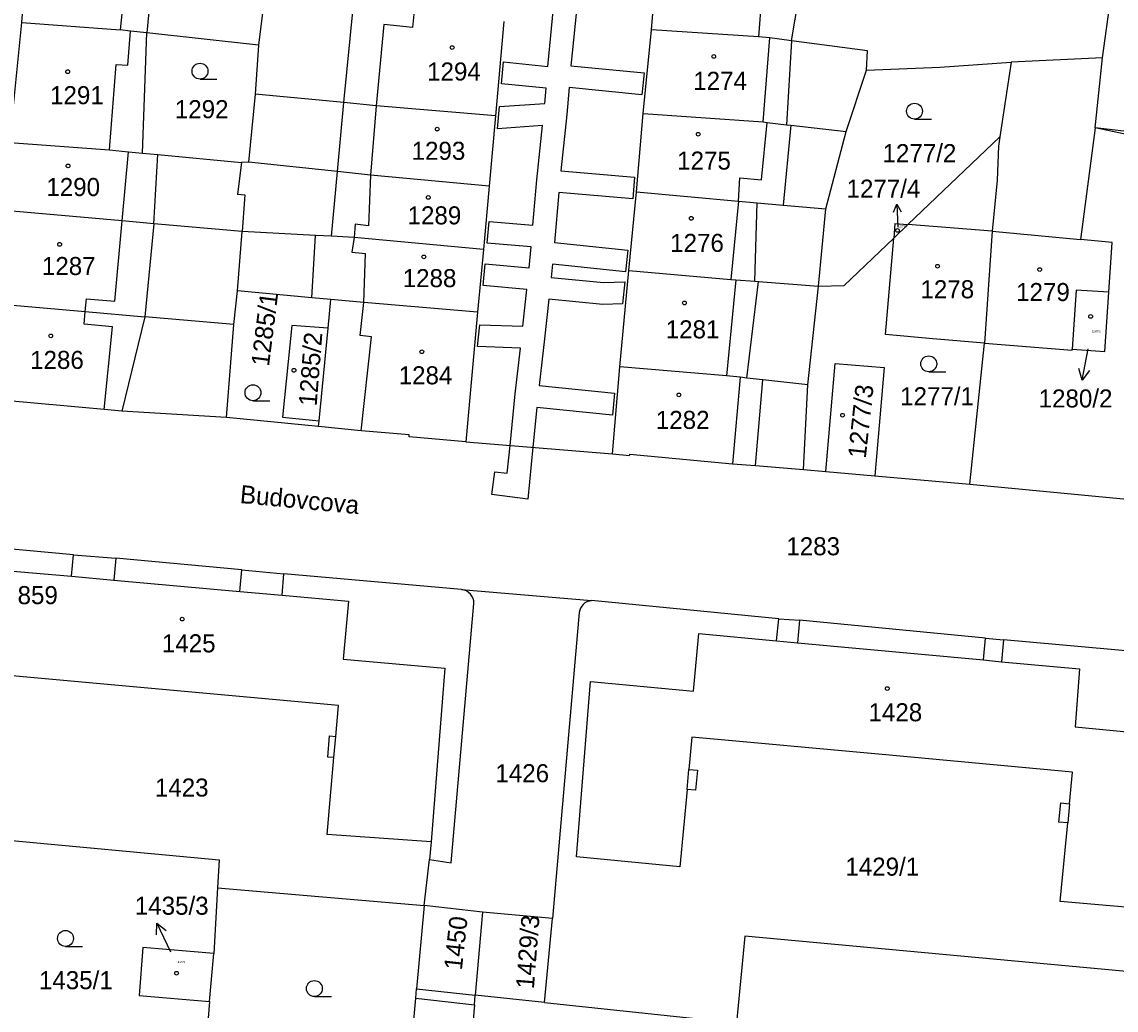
# Model space of a CAD drawing. Extents: x -755819 to -753140, y -1169796 to -1166000.
# Drawn here: x -755595.1 to -755492, y -1167320.5 to -1167227.4 of the extents above; entities that cross this region are included whole.
import ezdxf

# ---------------------------------------------------------------- set-up
doc = ezdxf.new("R2010")
doc.units = 0
for name, color, linetype in [('Vrstva 1', 7, 'Continuous'), ('Vrstva 15', 7, 'Continuous'), ('Vrstva 16', 7, 'Continuous'), ('Vrstva 17', 7, 'Continuous'), ('Vrstva 18', 7, 'Continuous'), ('Vrstva 19', 7, 'Continuous'), ('Vrstva 25', 7, 'Continuous'), ('Vrstva 27', 7, 'Continuous'), ('Vrstva 4', 7, 'Continuous'), ('Vrstva 6', 7, 'Continuous')]:
    doc.layers.add(name, color=color, linetype=linetype)

msp = doc.modelspace()

# ---------------------------------------------------------------- linework, layer by layer
at = {"layer": 'Vrstva 1'}
for p, q in [((-755595.07, -1167227.47), (-755594.03, -1167214.38)), ((-755582.08, -1167215.46), (-755583.31, -1167228.45)), ((-755535.78, -1167228.17), (-755534.86, -1167217.19)), ((-755522.6, -1167229.2), (-755520.73, -1167218.42)), ((-755493.31, -1167230.79), (-755492.14, -1167222.37)), ((-755572.26, -1167225.27), (-755572.79, -1167229.62)), ((-755596.22, -1167238.78), (-755595.07, -1167227.47)), ((-755595.07, -1167227.47), (-755585.82, -1167228.18)), ((-755549.7, -1167227.37), (-755550.46, -1167236.28)), ((-755584.85, -1167228.28), (-755585.82, -1167228.18)), ((-755583.31, -1167228.45), (-755584.85, -1167228.28)), ((-755583.73, -1167239.78), (-755583.31, -1167228.45)), ((-755572.79, -1167229.62), (-755583.31, -1167228.45)), ((-755536.55, -1167236.06), (-755535.78, -1167228.17)), ((-755525.71, -1167228.82), (-755535.78, -1167228.17)), ((-755572.79, -1167229.62), (-755573.09, -1167234.23)), ((-755524.63, -1167228.93), (-755525.71, -1167228.82)), ((-755522.6, -1167229.2), (-755524.63, -1167228.93)), ((-755515.45, -1167230.14), (-755522.6, -1167229.2)), ((-755515.52, -1167231.98), (-755515.45, -1167230.14)), ((-755508.61, -1167231.69), (-755501.92, -1167231.22)), ((-755501.92, -1167231.22), (-755502.97, -1167238.26)), ((-755493.31, -1167230.79), (-755501.92, -1167231.22)), ((-755493.98, -1167237.39), (-755493.31, -1167230.79)), ((-755517.44, -1167237.74), (-755515.52, -1167231.98)), ((-755515.52, -1167231.98), (-755508.61, -1167231.69)), ((-755573.09, -1167234.23), (-755573.72, -1167240.63)), ((-755564.76, -1167235.02), (-755573.09, -1167234.23)), ((-755561.72, -1167235.31), (-755564.76, -1167235.02)), ((-755550.46, -1167236.28), (-755561.72, -1167235.31)), ((-755550.46, -1167236.28), (-755551.06, -1167242.88)), ((-755537.19, -1167243.43), (-755536.55, -1167236.06)), ((-755536.55, -1167236.06), (-755525.26, -1167236.82)), ((-755525.26, -1167236.82), (-755524.9, -1167236.91)), ((-755524.9, -1167236.91), (-755523.07, -1167237.11)), ((-755523.07, -1167237.11), (-755522.67, -1167237.15)), ((-755522.67, -1167237.15), (-755517.44, -1167237.74)), ((-755519.35, -1167245.03), (-755517.44, -1167237.74)), ((-755493.98, -1167237.39), (-755495.36, -1167247.9)), ((-755483.37, -1167239.63), (-755493.98, -1167237.39)), ((-755596.22, -1167238.78), (-755586.81, -1167239.46)), ((-755502.97, -1167238.26), (-755503.1, -1167239.12)), ((-755586.81, -1167239.46), (-755585.02, -1167239.65)), ((-755585.02, -1167239.65), (-755583.73, -1167239.78)), ((-755583.73, -1167239.78), (-755582.28, -1167239.91)), ((-755582.28, -1167239.91), (-755574.4, -1167240.66)), ((-755503.1, -1167239.12), (-755503.23, -1167242.34)), ((-755574.4, -1167240.66), (-755574.78, -1167243.64)), ((-755573.72, -1167240.63), (-755574.4, -1167240.66)), ((-755565.36, -1167241.52), (-755573.72, -1167240.63)), ((-755562.25, -1167241.86), (-755565.36, -1167241.52)), ((-755551.06, -1167242.88), (-755562.25, -1167241.86)), ((-755551.06, -1167242.88), (-755551.6, -1167248.86)), ((-755503.23, -1167242.34), (-755503.68, -1167247.13)), ((-755574.78, -1167243.64), (-755574.07, -1167243.71)), ((-755574.07, -1167243.71), (-755574.34, -1167247.15)), ((-755537.9, -1167250.83), (-755537.19, -1167243.43)), ((-755537.19, -1167243.43), (-755527.6, -1167244.29)), ((-755527.6, -1167244.29), (-755525.82, -1167244.45)), ((-755525.82, -1167244.45), (-755523.39, -1167244.67)), ((-755523.39, -1167244.67), (-755519.35, -1167245.03)), ((-755520.06, -1167252.32), (-755519.35, -1167245.03)), ((-755585.62, -1167246.17), (-755596.7, -1167245.18)), ((-755582.66, -1167246.43), (-755585.62, -1167246.17)), ((-755574.34, -1167247.15), (-755582.66, -1167246.43)), ((-755512.85, -1167246.41), (-755512.97, -1167247.78)), ((-755512.85, -1167246.41), (-755511.63, -1167246.51)), ((-755503.68, -1167247.13), (-755504.41, -1167257.66)), ((-755574.77, -1167252.76), (-755574.34, -1167247.15)), ((-755567.43, -1167247.53), (-755574.34, -1167247.15)), ((-755565.92, -1167247.61), (-755567.43, -1167247.53)), ((-755563.77, -1167247.73), (-755565.92, -1167247.61)), ((-755551.6, -1167248.86), (-755563.77, -1167247.73)), ((-755513.73, -1167256.86), (-755512.97, -1167247.78)), ((-755492.39, -1167248.18), (-755495.36, -1167247.9)), ((-755551.6, -1167248.86), (-755552.16, -1167254.76)), ((-755492.71, -1167252.88), (-755492.39, -1167248.18)), ((-755538.76, -1167259.89), (-755537.9, -1167250.83)), ((-755537.9, -1167250.83), (-755528.31, -1167251.67)), ((-755528.31, -1167251.67), (-755527.82, -1167251.71)), ((-755527.82, -1167251.71), (-755526.05, -1167251.85)), ((-755526.05, -1167251.85), (-755525.71, -1167251.87)), ((-755525.71, -1167251.87), (-755520.06, -1167252.32)), ((-755575.11, -1167255.91), (-755574.77, -1167252.76)), ((-755567.76, -1167253.39), (-755574.77, -1167252.76)), ((-755521.06, -1167261.61), (-755520.06, -1167252.32)), ((-755495.78, -1167252.67), (-755496.17, -1167258.24)), ((-755492.71, -1167252.88), (-755495.78, -1167252.67)), ((-755493.09, -1167258.46), (-755492.71, -1167252.88)), ((-755597.48, -1167253.97), (-755589.12, -1167254.7)), ((-755565.97, -1167253.56), (-755567.76, -1167253.39)), ((-755566.22, -1167256.27), (-755565.97, -1167253.56)), ((-755562.88, -1167253.83), (-755565.97, -1167253.56)), ((-755552.16, -1167254.76), (-755562.88, -1167253.83)), ((-755589.12, -1167254.7), (-755583.49, -1167255.19)), ((-755575.11, -1167255.91), (-755583.49, -1167255.19)), ((-755552.16, -1167254.76), (-755553.25, -1167266.97)), ((-755575.81, -1167264.66), (-755575.11, -1167255.91)), ((-755569.65, -1167256), (-755570.52, -1167264.64)), ((-755566.22, -1167256.27), (-755569.65, -1167256)), ((-755567.09, -1167264.99), (-755566.22, -1167256.27)), ((-755509.27, -1167257.27), (-755513.73, -1167256.86)), ((-755504.41, -1167257.66), (-755509.27, -1167257.27)), ((-755505.81, -1167270.94), (-755504.41, -1167257.66)), ((-755504.41, -1167257.66), (-755496.17, -1167258.34)), ((-755496.17, -1167258.34), (-755496.17, -1167258.24)), ((-755496.17, -1167258.24), (-755493.09, -1167258.46)), ((-755539.46, -1167268.09), (-755538.76, -1167259.89)), ((-755528.7, -1167260.75), (-755538.76, -1167259.89)), ((-755519.36, -1167269.76), (-755518.47, -1167259.58)), ((-755518.47, -1167259.58), (-755513.85, -1167259.98)), ((-755513.85, -1167259.98), (-755514.74, -1167270.16)), ((-755527.44, -1167260.89), (-755528.7, -1167260.75)), ((-755526.8, -1167260.96), (-755527.44, -1167260.89)), ((-755525.29, -1167261.13), (-755526.8, -1167260.96)), ((-755521.06, -1167261.61), (-755525.29, -1167261.13)), ((-755521.45, -1167269.57), (-755521.06, -1167261.61)), ((-755587.34, -1167263.93), (-755598.35, -1167262.92)), ((-755585.65, -1167264.08), (-755587.34, -1167263.93)), ((-755575.81, -1167264.66), (-755585.65, -1167264.08)), ((-755567.14, -1167265.53), (-755575.81, -1167264.66)), ((-755570.52, -1167264.64), (-755567.09, -1167264.99)), ((-755567.14, -1167265.53), (-755567.09, -1167264.99)), ((-755563.13, -1167265.94), (-755567.14, -1167265.53)), ((-755558.6, -1167266.32), (-755563.13, -1167265.94)), ((-755558.61, -1167266.48), (-755558.6, -1167266.32)), ((-755553.25, -1167266.97), (-755558.61, -1167266.48)), ((-755553.25, -1167266.97), (-755539.46, -1167268.09)), ((-755539.46, -1167268.09), (-755537.85, -1167268.24)), ((-755537.85, -1167268.24), (-755537.83, -1167268.12)), ((-755537.83, -1167268.12), (-755528.16, -1167269.04)), ((-755528.16, -1167269.04), (-755525.98, -1167269.21)), ((-755525.98, -1167269.21), (-755521.45, -1167269.57)), ((-755521.45, -1167269.57), (-755519.36, -1167269.76)), ((-755519.36, -1167269.76), (-755514.74, -1167270.16)), ((-755514.74, -1167270.16), (-755505.81, -1167270.94)), ((-755505.81, -1167270.94), (-755488.72, -1167272.57)), ((-755590.22, -1167277.62), (-755598.23, -1167276.87)), ((-755590.22, -1167277.62), (-755586.24, -1167277.92)), ((-755574.37, -1167279.03), (-755586.24, -1167277.92)), ((-755574.37, -1167279.03), (-755570.39, -1167279.39)), ((-755553.68, -1167280.88), (-755570.39, -1167279.39)), ((-755553.68, -1167280.88), (-755541.44, -1167281.92)), ((-755523.8, -1167283.62), (-755541.44, -1167281.92)), ((-755554.63, -1167306.6), (-755552.5, -1167282.19)), ((-755542.58, -1167283.04), (-755545.11, -1167311.85)), ((-755523.99, -1167285.7), (-755523.8, -1167283.62)), ((-755523.8, -1167283.62), (-755521.83, -1167283.77)), ((-755504.32, -1167285.44), (-755521.83, -1167283.77)), ((-755531.81, -1167290.45), (-755531.32, -1167285.02)), ((-755531.32, -1167285.02), (-755523.99, -1167285.7)), ((-755504.32, -1167285.44), (-755502.64, -1167285.61)), ((-755502.64, -1167285.61), (-755502.83, -1167287.67)), ((-755483.86, -1167287.31), (-755502.64, -1167285.61)), ((-755502.83, -1167287.67), (-755495.48, -1167288.35)), ((-755495.48, -1167288.35), (-755495.87, -1167293.8)), ((-755565.26, -1167291.78), (-755597.44, -1167288.87)), ((-755542.85, -1167306.06), (-755541.51, -1167289.53)), ((-755541.51, -1167289.53), (-755531.81, -1167290.45)), ((-755565.52, -1167294.71), (-755565.26, -1167291.78)), ((-755495.87, -1167293.8), (-755486.26, -1167294.72)), ((-755566.25, -1167296.65), (-755566.09, -1167294.66)), ((-755566.09, -1167294.66), (-755565.52, -1167294.71)), ((-755531.98, -1167294.77), (-755532.26, -1167297.82)), ((-755514.06, -1167296.42), (-755531.98, -1167294.77)), ((-755496.12, -1167298.06), (-755514.06, -1167296.42)), ((-755566.31, -1167303.94), (-755565.69, -1167296.7)), ((-755565.69, -1167296.7), (-755566.25, -1167296.65)), ((-755532.26, -1167297.82), (-755531.45, -1167297.89)), ((-755531.45, -1167297.89), (-755531.62, -1167299.77)), ((-755496.4, -1167301.05), (-755496.12, -1167298.06)), ((-755532.43, -1167299.7), (-755533.1, -1167306.99)), ((-755531.62, -1167299.77), (-755532.43, -1167299.7)), ((-755497.41, -1167302.77), (-755497.23, -1167300.97)), ((-755497.23, -1167300.97), (-755496.4, -1167301.05)), ((-755496.58, -1167302.85), (-755497.41, -1167302.77)), ((-755497.29, -1167310.24), (-755496.58, -1167302.85)), ((-755601.97, -1167303.95), (-755576.51, -1167306.32)), ((-755556.52, -1167304.62), (-755566.31, -1167303.94)), ((-755556.52, -1167304.62), (-755556.7, -1167306.29)), ((-755576.51, -1167306.32), (-755576.65, -1167308.96)), ((-755557.18, -1167310.63), (-755556.7, -1167306.29)), ((-755556.7, -1167306.29), (-755554.63, -1167306.6)), ((-755533.1, -1167306.99), (-755542.85, -1167306.06)), ((-755576.65, -1167308.96), (-755557.18, -1167310.63)), ((-755557.18, -1167310.63), (-755557.9, -1167318.49)), ((-755551.68, -1167311.25), (-755557.18, -1167310.63)), ((-755487.4, -1167311.1), (-755497.29, -1167310.24)), ((-755551.68, -1167311.25), (-755552.38, -1167319.08)), ((-755545.11, -1167311.85), (-755551.68, -1167311.25)), ((-755545.87, -1167319.76), (-755545.11, -1167311.85)), ((-755527, -1167313.51), (-755527.77, -1167321.67)), ((-755486.66, -1167317.24), (-755527, -1167313.51)), ((-755583.67, -1167314.58), (-755584.03, -1167319.09)), ((-755577.01, -1167315.15), (-755583.67, -1167314.58)), ((-755577.39, -1167319.66), (-755577.01, -1167315.15)), ((-755584.03, -1167319.09), (-755577.39, -1167319.66)), ((-755557.98, -1167319.34), (-755557.9, -1167318.49)), ((-755552.45, -1167319.97), (-755552.38, -1167319.08)), ((-755545.87, -1167319.76), (-755552.38, -1167319.08)), ((-755559.43, -1167335.26), (-755557.98, -1167319.34)), ((-755557.98, -1167319.34), (-755552.45, -1167319.97)), ((-755552.45, -1167319.97), (-755553.02, -1167326.32)), ((-755545.87, -1167319.76), (-755529.57, -1167321.48))]:
    msp.add_line(p, q, dxfattribs=at)
for centre, radius, start, end in [((-755553.8, -1167282.17), 1.3, 359.2739, 84.7489), ((-755541.35, -1167283.15), 1.23, 94.16, 174.826)]:
    msp.add_arc(centre, radius, start, end, dxfattribs=at)
at = {"layer": 'Vrstva 16'}
for p, q in [((-755512.68, -1167244.6), (-755512.57, -1167246.76)), ((-755495.21, -1167261.15), (-755494.66, -1167258.2)), ((-755582.37, -1167312.29), (-755581.09, -1167315))]:
    msp.add_line(p, q, dxfattribs=at)
for points in [[(-755513, -1167245.34), (-755512.68, -1167244.6), (-755512.28, -1167245.3)], [(-755494.54, -1167260.26), (-755495.21, -1167261.15), (-755495.52, -1167260.07)], [(-755582.39, -1167313.4), (-755582.37, -1167312.29), (-755581.49, -1167312.98)]]:
    msp.add_lwpolyline(points, dxfattribs=at)
at = {"layer": 'Vrstva 25'}
for p, q in [((-755578.3, -1167232.81), (-755576.7, -1167232.81)), ((-755511.01, -1167236.58), (-755509.41, -1167236.58)), ((-755509.67, -1167260.37), (-755508.07, -1167260.37)), ((-755573.31, -1167263.09), (-755571.71, -1167263.09)), ((-755590.97, -1167314.48), (-755589.37, -1167314.48)), ((-755567.53, -1167319.2), (-755565.93, -1167319.2))]:
    msp.add_line(p, q, dxfattribs=at)
for centre, radius in [((-755554.55, -1167229.84), 0.175), ((-755529.91, -1167230.67), 0.175), ((-755578.3, -1167232.06), 0.75), ((-755590.76, -1167232.11), 0.175), ((-755511.01, -1167235.83), 0.75), ((-755555.96, -1167237.52), 0.175), ((-755531.38, -1167238), 0.175), ((-755590.73, -1167240.98), 0.175), ((-755556.8, -1167243.95), 0.175), ((-755532.03, -1167245.92), 0.175), ((-755512.6, -1167247.06), 0.175), ((-755591.52, -1167248.37), 0.175), ((-755557.22, -1167249.55), 0.175), ((-755508.84, -1167250.43), 0.175), ((-755499.22, -1167250.74), 0.175), ((-755532.68, -1167253.89), 0.175), ((-755494.42, -1167255.16), 0.175), ((-755592.36, -1167256.99), 0.175), ((-755557.41, -1167258.48), 0.175), ((-755509.67, -1167259.62), 0.75), ((-755569.45, -1167260.23), 0.175), ((-755573.31, -1167262.34), 0.75), ((-755533.2, -1167262.55), 0.175), ((-755517.78, -1167264.46), 0.175), ((-755579.97, -1167283.66), 0.175), ((-755513.57, -1167290.2), 0.175), ((-755590.97, -1167313.73), 0.75), ((-755580.51, -1167317.01), 0.175), ((-755567.53, -1167318.45), 0.75)]:
    msp.add_circle(centre, radius, dxfattribs=at)
at = {"layer": 'Vrstva 27'}
for p, q in [((-755542.59, -1167223.68), (-755543.36, -1167231.56)), ((-755545.53, -1167231.61), (-755544.88, -1167224.65)), ((-755549.9, -1167233.24), (-755549.72, -1167231.19)), ((-755549.72, -1167231.19), (-755545.53, -1167231.61)), ((-755543.36, -1167231.56), (-755536.48, -1167232.23)), ((-755536.48, -1167232.23), (-755536.68, -1167234.28)), ((-755545.71, -1167233.66), (-755549.9, -1167233.24)), ((-755545.83, -1167235.09), (-755545.71, -1167233.66)), ((-755543.54, -1167233.61), (-755543.74, -1167236.15)), ((-755536.68, -1167234.28), (-755543.54, -1167233.61)), ((-755550.27, -1167237.48), (-755550.08, -1167235.4)), ((-755550.08, -1167235.4), (-755545.83, -1167235.09)), ((-755543.74, -1167236.15), (-755544.32, -1167241.45)), ((-755546.03, -1167237.17), (-755550.27, -1167237.48)), ((-755546.59, -1167242.28), (-755546.03, -1167237.17)), ((-755544.32, -1167241.45), (-755537.37, -1167242.03)), ((-755546.95, -1167246.56), (-755546.59, -1167242.28)), ((-755537.37, -1167242.03), (-755537.55, -1167244.09)), ((-755544.52, -1167243.5), (-755544.92, -1167248.2)), ((-755537.55, -1167244.09), (-755544.52, -1167243.5)), ((-755551.25, -1167248.27), (-755551.06, -1167246.21)), ((-755551.06, -1167246.21), (-755546.95, -1167246.56)), ((-755547.12, -1167248.61), (-755551.25, -1167248.27)), ((-755547.31, -1167250.57), (-755547.12, -1167248.61)), ((-755544.92, -1167248.2), (-755538.02, -1167248.92)), ((-755538.02, -1167248.92), (-755538.22, -1167250.97)), ((-755551.62, -1167252.24), (-755551.43, -1167250.19)), ((-755551.43, -1167250.19), (-755547.31, -1167250.57)), ((-755545.11, -1167250.25), (-755545.24, -1167251.49)), ((-755538.22, -1167250.97), (-755545.11, -1167250.25)), ((-755547.53, -1167252.62), (-755551.62, -1167252.24)), ((-755545.24, -1167251.49), (-755540.3, -1167251.96)), ((-755540.3, -1167251.96), (-755538.3, -1167251.9)), ((-755538.3, -1167251.9), (-755538.5, -1167253.96)), ((-755547.89, -1167256.08), (-755547.53, -1167252.62)), ((-755545.46, -1167253.54), (-755545.85, -1167257.26)), ((-755540.36, -1167254.02), (-755545.46, -1167253.54)), ((-755538.5, -1167253.96), (-755540.36, -1167254.02)), ((-755552.15, -1167258), (-755551.96, -1167255.94)), ((-755551.96, -1167255.94), (-755547.89, -1167256.08)), ((-755545.85, -1167257.26), (-755546.35, -1167261.65)), ((-755548.12, -1167258.13), (-755552.15, -1167258)), ((-755548.61, -1167262.46), (-755548.12, -1167258.13)), ((-755549.1, -1167267.31), (-755548.61, -1167262.46)), ((-755546.35, -1167261.65), (-755539.27, -1167262.39)), ((-755539.27, -1167262.39), (-755539.45, -1167264.46)), ((-755546.57, -1167263.72), (-755546.94, -1167267.48)), ((-755539.45, -1167264.46), (-755546.57, -1167263.72)), ((-755549.36, -1167269.93), (-755549.1, -1167267.31)), ((-755546.94, -1167267.48), (-755547.42, -1167272.35)), ((-755550.8, -1167271.92), (-755550.52, -1167269.78)), ((-755550.52, -1167269.78), (-755549.36, -1167269.93)), ((-755547.42, -1167272.35), (-755550.8, -1167271.92))]:
    msp.add_line(p, q, dxfattribs=at)
at = {"layer": 'Vrstva 4'}
for p, q in [((-755584.82, -1167218.13), (-755585.82, -1167228.18)), ((-755525.12, -1167221.28), (-755525.71, -1167228.82)), ((-755564.76, -1167235.02), (-755563.89, -1167226.12)), ((-755558.17, -1167226.7), (-755558.3, -1167227.94)), ((-755585.1, -1167231.51), (-755584.85, -1167228.28)), ((-755561, -1167227.66), (-755561.72, -1167235.31)), ((-755558.3, -1167227.94), (-755561, -1167227.66)), ((-755525.26, -1167236.82), (-755524.63, -1167228.93)), ((-755522.6, -1167229.2), (-755523.07, -1167237.11)), ((-755586.81, -1167239.46), (-755586.18, -1167231.42)), ((-755586.18, -1167231.42), (-755585.1, -1167231.51)), ((-755565.36, -1167241.52), (-755564.76, -1167235.02)), ((-755561.72, -1167235.31), (-755562.25, -1167241.86)), ((-755525.43, -1167242.28), (-755524.9, -1167236.91)), ((-755522.67, -1167237.15), (-755523.39, -1167244.67)), ((-755482.38, -1167238.73), (-755493.98, -1167237.39)), ((-755585.62, -1167246.17), (-755585.02, -1167239.65)), ((-755582.66, -1167246.43), (-755582.28, -1167239.91)), ((-755565.92, -1167247.61), (-755565.36, -1167241.52)), ((-755562.25, -1167241.86), (-755562.42, -1167246.61)), ((-755527.6, -1167244.29), (-755527.45, -1167242.12)), ((-755527.45, -1167242.12), (-755525.43, -1167242.28)), ((-755527.6, -1167244.29), (-755528.31, -1167251.67)), ((-755526.05, -1167251.85), (-755525.82, -1167244.45)), ((-755586.31, -1167253.73), (-755585.62, -1167246.17)), ((-755582.66, -1167246.43), (-755583.49, -1167255.19)), ((-755563.69, -1167246.47), (-755563.77, -1167247.73)), ((-755562.42, -1167246.61), (-755563.69, -1167246.47)), ((-755503.68, -1167247.13), (-755511.63, -1167246.51)), ((-755503.68, -1167247.13), (-755495.36, -1167247.9)), ((-755567.76, -1167253.39), (-755567.43, -1167247.53)), ((-755563.77, -1167247.73), (-755564.01, -1167249.09)), ((-755564.01, -1167249.09), (-755562.72, -1167249.23)), ((-755562.88, -1167253.83), (-755562.72, -1167249.23)), ((-755527.82, -1167251.71), (-755528.7, -1167260.75)), ((-755526.8, -1167260.96), (-755525.71, -1167251.87)), ((-755589.12, -1167254.7), (-755589, -1167253.49)), ((-755589, -1167253.49), (-755586.31, -1167253.73)), ((-755563.23, -1167256.95), (-755562.88, -1167253.83)), ((-755589.22, -1167255.9), (-755589.12, -1167254.7)), ((-755583.49, -1167255.19), (-755585.65, -1167264.08)), ((-755586.54, -1167256.15), (-755589.22, -1167255.9)), ((-755587.34, -1167263.93), (-755586.54, -1167256.15)), ((-755562.14, -1167257.07), (-755563.23, -1167256.95)), ((-755563.13, -1167265.94), (-755562.14, -1167257.07)), ((-755527.44, -1167260.89), (-755528.16, -1167269.04)), ((-755525.98, -1167269.21), (-755525.29, -1167261.13)), ((-755590.4, -1167279.63), (-755590.22, -1167277.62)), ((-755586.24, -1167277.92), (-755586.42, -1167279.99)), ((-755596.66, -1167279.07), (-755590.4, -1167279.63)), ((-755574.55, -1167281.06), (-755574.37, -1167279.03)), ((-755590.4, -1167279.63), (-755586.42, -1167279.99)), ((-755586.42, -1167279.99), (-755574.55, -1167281.06)), ((-755570.57, -1167281.42), (-755570.39, -1167279.39)), ((-755574.55, -1167281.06), (-755570.57, -1167281.42)), ((-755570.57, -1167281.42), (-755564.33, -1167281.98)), ((-755564.33, -1167281.98), (-755564.82, -1167287.44)), ((-755521.83, -1167283.77), (-755522.02, -1167285.89)), ((-755523.99, -1167285.7), (-755522.02, -1167285.89)), ((-755522.02, -1167285.89), (-755504.51, -1167287.51)), ((-755504.51, -1167287.51), (-755504.32, -1167285.44)), ((-755564.82, -1167287.44), (-755555.23, -1167288.28)), ((-755555.23, -1167288.28), (-755556.52, -1167304.62)), ((-755504.51, -1167287.51), (-755502.83, -1167287.67)), ((-755565.69, -1167296.7), (-755565.52, -1167294.71)), ((-755532.43, -1167299.7), (-755532.26, -1167297.82)), ((-755496.4, -1167301.05), (-755496.58, -1167302.85)), ((-755557.9, -1167318.49), (-755552.38, -1167319.08))]:
    msp.add_line(p, q, dxfattribs=at)
at = {"layer": 'Vrstva 6'}
for p, q in [((-755502.97, -1167238.26), (-755511.63, -1167246.51)), ((-755511.63, -1167246.51), (-755512.97, -1167247.78)), ((-755517.64, -1167252.23), (-755512.97, -1167247.78)), ((-755520.06, -1167252.32), (-755517.64, -1167252.23)), ((-755576.65, -1167308.96), (-755577.01, -1167315.15)), ((-755577.39, -1167319.66), (-755578.6, -1167333.75))]:
    msp.add_line(p, q, dxfattribs=at)

# ---------------------------------------------------------------- texts
at = {"layer": 'Vrstva 15'}
msp.add_text('Budovcova', height=1.7, rotation=354.6036, dxfattribs=at).set_placement((-755574.59, -1167272.72))
at = {"layer": 'Vrstva 16'}
for s, p in [('1277/4', (-755517.41, -1167243.97)), ('1280/2', (-755499.32, -1167263.73)), ('1435/3', (-755584.44, -1167311.5))]:
    msp.add_text(s, height=1.7, dxfattribs=at).set_placement(p)
at = {"layer": 'Vrstva 17'}
msp.add_text('859', height=1.7, dxfattribs=at).set_placement((-755595.48, -1167282.25))
at = {"layer": 'Vrstva 18'}
for s, p in [('1292', (-755580.67, -1167236.49)), ('1277/2', (-755514.02, -1167240.63)), ('1277/1', (-755512.36, -1167263.52)), ('1283', (-755523.08, -1167277.65)), ('1426', (-755550.48, -1167299.02)), ('1423', (-755582.55, -1167300.37)), ('1429/1', (-755517.52, -1167307.82)), ('1435/1', (-755593.47, -1167318.51))]:
    msp.add_text(s, height=1.7, dxfattribs=at).set_placement(p)
for s, rotation, p in [('1285/1', 82.7924, (-755571.81, -1167259.92)), ('1450', 83.7091, (-755553.64, -1167316.77)), ('1429/3', 85.4853, (-755546.86, -1167318.53))]:
    msp.add_text(s, height=1.7, rotation=rotation, dxfattribs=at).set_placement(p)
at = {"layer": 'Vrstva 19'}
for s, height, p in [('1294', 1.7, (-755556.91, -1167232.94)), ('1274', 1.7, (-755531.85, -1167233.82)), ('1291', 1.7, (-755592.42, -1167235.17)), ('1293', 1.7, (-755558.37, -1167240.41)), ('1275', 1.7, (-755533.36, -1167241.33)), ('1290', 1.7, (-755592.77, -1167243.82)), ('1289', 1.7, (-755558.75, -1167246.49)), ('1277/4', 0.2, (-755512.52, -1167246.76)), ('1276', 1.7, (-755534.02, -1167249.08)), ('1287', 1.7, (-755593.19, -1167251.26)), ('1288', 1.7, (-755559.21, -1167252.4)), ('1278', 1.7, (-755510.45, -1167253.45)), ('1279', 1.7, (-755501.44, -1167253.71)), ('1281', 1.7, (-755534.44, -1167257.22)), ('1280/2', 0.2, (-755494.32, -1167256.65)), ('1286', 1.7, (-755594.3, -1167260.1)), ('1284', 1.7, (-755559.59, -1167261.55)), ('1282', 1.7, (-755535.37, -1167265.75)), ('1425', 1.7, (-755581.89, -1167286.79)), ('1428', 1.7, (-755515.34, -1167293.28)), ('1435/3', 0.2, (-755580.55, -1167316.05))]:
    msp.add_text(s, height=height, dxfattribs=at).set_placement(p)
for s, rotation, p in [('1285/2', 85.4853, (-755567.32, -1167263.65)), ('1277/3', 83.8237, (-755515.6, -1167268.58))]:
    msp.add_text(s, height=1.7, rotation=rotation, dxfattribs=at).set_placement(p)

doc.saveas('drawing.dxf')
